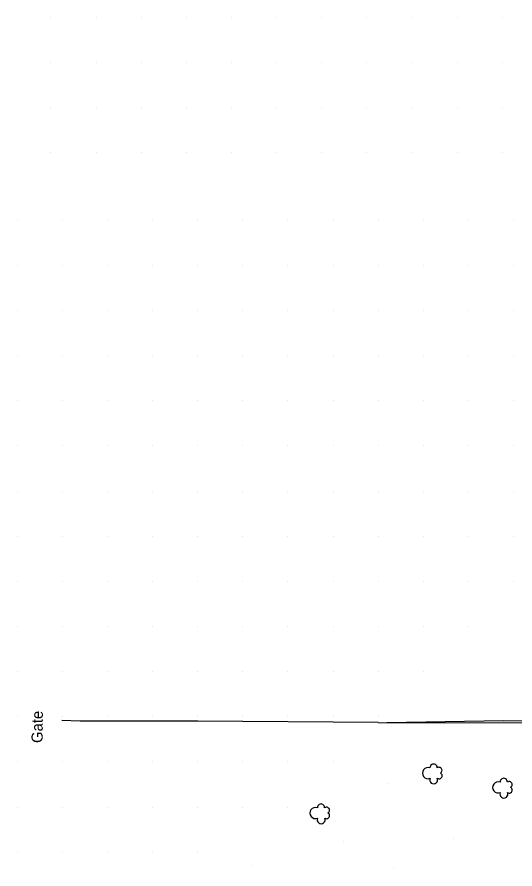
# Model space of a CAD drawing. Extents: x 19528164 to 19545171, y 7585743 to 7602745.
# Drawn here: x 19542455 to 19542675.6, y 7596817.6 to 7597195 of the extents above; entities that cross this region are included whole.
import ezdxf

# ---------------------------------------------------------------- set-up
doc = ezdxf.new("R2010")
doc.units = 0
for name, color, linetype in [('PhoFence', 7, 'Continuous'), ('PhoISAEPoints', 7, 'Continuous'), ('PhoNotesDesign', 7, 'Continuous'), ('PhoVegetation', 7, 'Continuous'), ('SurBreakLine', 7, 'Continuous'), ('SurEdgeEntranceUnpaved', 7, 'Continuous')]:
    doc.layers.add(name, color=color, linetype=linetype)

msp = doc.modelspace()

# ---------------------------------------------------------------- linework, layer by layer
at = {"layer": 'PhoFence'}
for points in [[(19542614.96, 7596882.41), (19542822.15, 7596882.08), (19542813, 7596985.55), (19542803, 7597074.91), (19542797.73, 7597139.29)], [(19542614.96, 7596882.41), (19542535.07, 7596883.14), (19542483, 7596883.06), (19542474.89, 7596883.31)]]:
    msp.add_lwpolyline(points, dxfattribs=at)
at = {"layer": 'PhoISAEPoints'}
for p, q in [((19542470, 7597195), (19542470, 7597195)), ((19542490, 7597195), (19542490, 7597195)), ((19542510, 7597195), (19542510, 7597195)), ((19542530, 7597195), (19542530, 7597195)), ((19542550, 7597195), (19542550, 7597195)), ((19542570, 7597195), (19542570, 7597195)), ((19542590, 7597195), (19542590, 7597195)), ((19542610, 7597195), (19542610, 7597195)), ((19542630, 7597195), (19542630, 7597195)), ((19542650, 7597195), (19542650, 7597195)), ((19542670, 7597195), (19542670, 7597195)), ((19542470, 7597175), (19542470, 7597175)), ((19542490, 7597175), (19542490, 7597175)), ((19542510, 7597175), (19542510, 7597175)), ((19542530, 7597175), (19542530, 7597175)), ((19542550, 7597175), (19542550, 7597175)), ((19542570, 7597175), (19542570, 7597175)), ((19542590, 7597175), (19542590, 7597175)), ((19542610, 7597175), (19542610, 7597175)), ((19542630, 7597175), (19542630, 7597175)), ((19542650, 7597175), (19542650, 7597175)), ((19542670, 7597175), (19542670, 7597175)), ((19542470, 7597155), (19542470, 7597155)), ((19542490, 7597155), (19542490, 7597155)), ((19542510, 7597155), (19542510, 7597155)), ((19542530, 7597155), (19542530, 7597155)), ((19542550, 7597155), (19542550, 7597155)), ((19542570, 7597155), (19542570, 7597155)), ((19542590, 7597155), (19542590, 7597155)), ((19542610, 7597155), (19542610, 7597155)), ((19542630, 7597155), (19542630, 7597155)), ((19542650, 7597155), (19542650, 7597155)), ((19542670, 7597155), (19542670, 7597155)), ((19542470, 7597135), (19542470, 7597135)), ((19542490, 7597135), (19542490, 7597135)), ((19542510, 7597135), (19542510, 7597135)), ((19542530, 7597135), (19542530, 7597135)), ((19542550, 7597135), (19542550, 7597135)), ((19542570, 7597135), (19542570, 7597135)), ((19542590, 7597135), (19542590, 7597135)), ((19542610, 7597135), (19542610, 7597135)), ((19542630, 7597135), (19542630, 7597135)), ((19542650, 7597135), (19542650, 7597135)), ((19542670, 7597135), (19542670, 7597135)), ((19542455, 7597105), (19542455, 7597105)), ((19542475, 7597105), (19542475, 7597105)), ((19542495, 7597105), (19542495, 7597105)), ((19542515, 7597105), (19542515, 7597105)), ((19542535, 7597105), (19542535, 7597105)), ((19542555, 7597105), (19542555, 7597105)), ((19542575, 7597105), (19542575, 7597105)), ((19542595, 7597105), (19542595, 7597105)), ((19542615, 7597105), (19542615, 7597105)), ((19542635, 7597105), (19542635, 7597105)), ((19542655, 7597105), (19542655, 7597105)), ((19542675, 7597105), (19542675, 7597105)), ((19542455, 7597085), (19542455, 7597085)), ((19542475, 7597085), (19542475, 7597085)), ((19542495, 7597085), (19542495, 7597085)), ((19542515, 7597085), (19542515, 7597085)), ((19542535, 7597085), (19542535, 7597085)), ((19542555, 7597085), (19542555, 7597085)), ((19542575, 7597085), (19542575, 7597085)), ((19542595, 7597085), (19542595, 7597085)), ((19542615, 7597085), (19542615, 7597085)), ((19542635, 7597085), (19542635, 7597085)), ((19542655, 7597085), (19542655, 7597085)), ((19542675, 7597085), (19542675, 7597085)), ((19542455, 7597065), (19542455, 7597065)), ((19542475, 7597065), (19542475, 7597065)), ((19542495, 7597065), (19542495, 7597065)), ((19542515, 7597065), (19542515, 7597065)), ((19542535, 7597065), (19542535, 7597065)), ((19542555, 7597065), (19542555, 7597065)), ((19542575, 7597065), (19542575, 7597065)), ((19542595, 7597065), (19542595, 7597065)), ((19542615, 7597065), (19542615, 7597065)), ((19542635, 7597065), (19542635, 7597065)), ((19542655, 7597065), (19542655, 7597065)), ((19542675, 7597065), (19542675, 7597065)), ((19542455, 7597045), (19542455, 7597045)), ((19542475, 7597045), (19542475, 7597045)), ((19542495, 7597045), (19542495, 7597045)), ((19542515, 7597045), (19542515, 7597045)), ((19542535, 7597045), (19542535, 7597045)), ((19542555, 7597045), (19542555, 7597045)), ((19542575, 7597045), (19542575, 7597045)), ((19542595, 7597045), (19542595, 7597045)), ((19542615, 7597045), (19542615, 7597045)), ((19542635, 7597045), (19542635, 7597045)), ((19542655, 7597045), (19542655, 7597045)), ((19542675, 7597045), (19542675, 7597045)), ((19542455, 7597025), (19542455, 7597025)), ((19542475, 7597025), (19542475, 7597025)), ((19542495, 7597025), (19542495, 7597025)), ((19542515, 7597025), (19542515, 7597025)), ((19542535, 7597025), (19542535, 7597025)), ((19542555, 7597025), (19542555, 7597025)), ((19542575, 7597025), (19542575, 7597025)), ((19542595, 7597025), (19542595, 7597025)), ((19542615, 7597025), (19542615, 7597025)), ((19542635, 7597025), (19542635, 7597025)), ((19542655, 7597025), (19542655, 7597025)), ((19542675, 7597025), (19542675, 7597025)), ((19542455, 7597005), (19542455, 7597005)), ((19542475, 7597005), (19542475, 7597005)), ((19542495, 7597005), (19542495, 7597005)), ((19542515, 7597005), (19542515, 7597005)), ((19542535, 7597005), (19542535, 7597005)), ((19542555, 7597005), (19542555, 7597005)), ((19542575, 7597005), (19542575, 7597005)), ((19542595, 7597005), (19542595, 7597005)), ((19542615, 7597005), (19542615, 7597005)), ((19542635, 7597005), (19542635, 7597005)), ((19542655, 7597005), (19542655, 7597005)), ((19542675, 7597005), (19542675, 7597005)), ((19542455, 7596985), (19542455, 7596985)), ((19542475, 7596985), (19542475, 7596985)), ((19542495, 7596985), (19542495, 7596985)), ((19542515, 7596985), (19542515, 7596985)), ((19542535, 7596985), (19542535, 7596985)), ((19542555, 7596985), (19542555, 7596985)), ((19542575, 7596985), (19542575, 7596985)), ((19542595, 7596985), (19542595, 7596985)), ((19542615, 7596985), (19542615, 7596985)), ((19542635, 7596985), (19542635, 7596985)), ((19542655, 7596985), (19542655, 7596985)), ((19542675, 7596985), (19542675, 7596985)), ((19542455, 7596965), (19542455, 7596965)), ((19542475, 7596965), (19542475, 7596965)), ((19542495, 7596965), (19542495, 7596965)), ((19542515, 7596965), (19542515, 7596965)), ((19542535, 7596965), (19542535, 7596965)), ((19542555, 7596965), (19542555, 7596965)), ((19542575, 7596965), (19542575, 7596965)), ((19542595, 7596965), (19542595, 7596965)), ((19542615, 7596965), (19542615, 7596965)), ((19542635, 7596965), (19542635, 7596965)), ((19542655, 7596965), (19542655, 7596965)), ((19542675, 7596965), (19542675, 7596965)), ((19542455, 7596945), (19542455, 7596945)), ((19542475, 7596945), (19542475, 7596945)), ((19542495, 7596945), (19542495, 7596945)), ((19542515, 7596945), (19542515, 7596945)), ((19542535, 7596945), (19542535, 7596945)), ((19542555, 7596945), (19542555, 7596945)), ((19542575, 7596945), (19542575, 7596945)), ((19542595, 7596945), (19542595, 7596945)), ((19542615, 7596945), (19542615, 7596945)), ((19542635, 7596945), (19542635, 7596945)), ((19542655, 7596945), (19542655, 7596945)), ((19542675, 7596945), (19542675, 7596945)), ((19542455, 7596925), (19542455, 7596925)), ((19542475, 7596925), (19542475, 7596925)), ((19542495, 7596925), (19542495, 7596925)), ((19542515, 7596925), (19542515, 7596925)), ((19542535, 7596925), (19542535, 7596925)), ((19542555, 7596925), (19542555, 7596925)), ((19542575, 7596925), (19542575, 7596925)), ((19542595, 7596925), (19542595, 7596925)), ((19542615, 7596925), (19542615, 7596925)), ((19542635, 7596925), (19542635, 7596925)), ((19542655, 7596925), (19542655, 7596925)), ((19542455, 7596905), (19542455, 7596905)), ((19542475, 7596905), (19542475, 7596905)), ((19542495, 7596905), (19542495, 7596905)), ((19542515, 7596905), (19542515, 7596905)), ((19542535, 7596905), (19542535, 7596905)), ((19542555, 7596905), (19542555, 7596905)), ((19542575, 7596905), (19542575, 7596905)), ((19542595, 7596905), (19542595, 7596905)), ((19542615, 7596905), (19542615, 7596905)), ((19542635, 7596905), (19542635, 7596905)), ((19542455, 7596885), (19542455, 7596885)), ((19542475, 7596885), (19542475, 7596885)), ((19542495, 7596885), (19542495, 7596885)), ((19542515, 7596885), (19542515, 7596885)), ((19542535, 7596885), (19542535, 7596885)), ((19542555, 7596885), (19542555, 7596885)), ((19542575, 7596885), (19542575, 7596885)), ((19542595, 7596885), (19542595, 7596885)), ((19542595, 7596885), (19542595, 7596885)), ((19542615, 7596885), (19542615, 7596885)), ((19542455, 7596865), (19542455, 7596865)), ((19542475, 7596865), (19542475, 7596865)), ((19542495, 7596865), (19542495, 7596865)), ((19542515, 7596865), (19542515, 7596865)), ((19542535, 7596865), (19542535, 7596865)), ((19542555, 7596865), (19542555, 7596865)), ((19542575, 7596865), (19542575, 7596865)), ((19542595, 7596865), (19542595, 7596865)), ((19542455, 7596845), (19542455, 7596845)), ((19542475, 7596845), (19542475, 7596845)), ((19542495, 7596845), (19542495, 7596845)), ((19542515, 7596845), (19542515, 7596845)), ((19542535, 7596845), (19542535, 7596845)), ((19542555, 7596845), (19542555, 7596845)), ((19542575, 7596845), (19542575, 7596845)), ((19542455, 7596825), (19542455, 7596825)), ((19542475, 7596825), (19542475, 7596825)), ((19542495, 7596825), (19542495, 7596825)), ((19542515, 7596825), (19542515, 7596825)), ((19542535, 7596825), (19542535, 7596825))]:
    msp.add_line(p, q, dxfattribs=at)
at = {"layer": 'PhoVegetation'}
for centre, radius, start, end in [((19542637.08, 7596860.05), 2.46, 68.7679, 292.3578), ((19542639.57, 7596862.47), 1.6, 356.5611, 184.5647), ((19542641.96, 7596861.29), 1.34, 297.087, 125.9662), ((19542642.02, 7596858.88), 1.34, 233.313, 65.8852), ((19542639.62, 7596857.06), 1.76, 156.0453, 25.0804), ((19542668.17, 7596853.73), 2.46, 68.7679, 292.3578), ((19542670.66, 7596856.15), 1.6, 356.5611, 184.5647), ((19542673.04, 7596854.97), 1.34, 297.087, 125.9662), ((19542670.71, 7596850.74), 1.76, 156.0453, 25.0804), ((19542673.1, 7596852.56), 1.34, 233.313, 65.8852), ((19542587.21, 7596842.38), 2.46, 68.7679, 292.3578), ((19542589.7, 7596844.8), 1.6, 356.5611, 184.5647), ((19542592.09, 7596843.62), 1.34, 297.087, 125.9662), ((19542589.76, 7596839.39), 1.76, 156.0453, 25.0804), ((19542592.15, 7596841.21), 1.34, 233.313, 65.8852)]:
    msp.add_arc(centre, radius, start, end, dxfattribs=at)
at = {"layer": 'SurBreakLine'}
msp.add_lwpolyline([(19542823.16, 7596883.47), (19542792.97, 7596881.8), (19542756.21, 7596882.29), (19542712.09, 7596882.55), (19542670.5, 7596883.26), (19542618.78, 7596882.32)], dxfattribs=at)
msp.add_lwpolyline([(19542823.16, 7596883.47), (19542792.97, 7596881.8), (19542756.21, 7596882.29), (19542712.09, 7596882.55), (19542670.5, 7596883.26), (19542618.78, 7596882.32)], dxfattribs=at)
msp.add_lwpolyline([(19542823.16, 7596883.47), (19542792.97, 7596881.8), (19542756.21, 7596882.29), (19542712.09, 7596882.55), (19542670.5, 7596883.26), (19542618.78, 7596882.32)], dxfattribs=at)
at = {"layer": 'SurEdgeEntranceUnpaved'}
for p, q in [((19542675, 7597005), (19542675, 7597005)), ((19542675, 7596985), (19542675, 7596985)), ((19542655, 7596965), (19542655, 7596965)), ((19542675, 7596965), (19542675, 7596965)), ((19542635, 7596945), (19542635, 7596945)), ((19542655, 7596945), (19542655, 7596945)), ((19542675, 7596945), (19542675, 7596945)), ((19542615, 7596925), (19542615, 7596925)), ((19542635, 7596925), (19542635, 7596925)), ((19542655, 7596925), (19542655, 7596925)), ((19542595, 7596905), (19542595, 7596905)), ((19542615, 7596905), (19542615, 7596905)), ((19542635, 7596905), (19542635, 7596905)), ((19542575, 7596885), (19542575, 7596885)), ((19542595, 7596885), (19542595, 7596885)), ((19542595, 7596885), (19542595, 7596885)), ((19542615, 7596885), (19542615, 7596885)), ((19542555, 7596865), (19542555, 7596865)), ((19542575, 7596865), (19542575, 7596865)), ((19542595, 7596865), (19542595, 7596865)), ((19542618.93, 7596855.47), (19542618.93, 7596855.47)), ((19542535, 7596845), (19542535, 7596845)), ((19542555, 7596845), (19542555, 7596845)), ((19542575, 7596845), (19542575, 7596845)), ((19542599.5, 7596829.89), (19542599.5, 7596829.89)), ((19542648.52, 7596831.06), (19542648.52, 7596831.06)), ((19542515, 7596825), (19542515, 7596825)), ((19542535, 7596825), (19542535, 7596825)), ((19542559.07, 7596819.21), (19542559.07, 7596819.21)), ((19542621.69, 7596817.6), (19542621.69, 7596817.6))]:
    msp.add_line(p, q, dxfattribs=at)

# ---------------------------------------------------------------- texts
at = {"layer": 'PhoNotesDesign'}
msp.add_text('Gate', height=4.92, rotation=89.5617, dxfattribs=at).set_placement((19542466.33, 7596873.38))

doc.saveas('drawing.dxf')
